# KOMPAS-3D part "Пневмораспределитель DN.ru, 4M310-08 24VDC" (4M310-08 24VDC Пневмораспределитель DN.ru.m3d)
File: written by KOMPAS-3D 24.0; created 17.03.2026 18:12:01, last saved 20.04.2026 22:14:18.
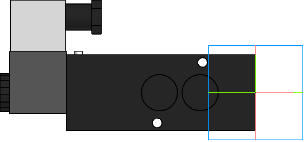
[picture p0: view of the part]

Document properties: Автор: R2D2; Полное имя файла: E:\Работа\Зайцев\Аксессуары для пневмоприводов\Пневмораспределители DN.ru\4М310-08 NAMUR Пневмораспределитель DN.RU\4М310-08 24VDC NAMUR Пневмораспределитель DN.RU\4M310-08 24VDC Пневмораспределитель DN.ru.m3d

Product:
- Part/product: Пневмораспределитель DN.ru  | designation 4M310-08 24VDC
    Масса: 0.35
    Раздел спецификации: Прочие изделия
    Примечание: D290-00330

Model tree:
1. Операция без истории:1

Expressions: 4M310-08 24VDC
